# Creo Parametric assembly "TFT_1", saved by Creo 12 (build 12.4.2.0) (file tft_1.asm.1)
Units: Custom; MM, KILOGRAM, SECS

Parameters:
  PTC_WM_ITERATION = "0"
  PTC_WM_VERSION = "-.0"
  PTC_WM_LIFECYCLE_STATE = "In Work"
  PTC_WM_LIFECYCLE = "MO_CADDocument"
  PTC_WM_CREATED_BY = "Maximilian Roepper (Z0017RMS: MO)"
  PTC_WM_CREATED_ON = "18-Sep-26 11:36:42 AM"
  PTC_WM_MODIFIED_BY = "Maximilian Roepper (Z0017RMS: MO)"
  PTC_WM_MODIFIED_ON = "18-Sep-26 11:36:46 AM"
  PDMLINKNUMBER = "PDM000071455268"
  PTC_WM_NUMBER = "PDM000071455268"

Other parameters: WEIGHT, WEIGHT_FACTOR, WEIGHT_ADD, MC_ERRORS, SUPPLIER

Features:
  1. coordinate system
  2. imported feature
  3. component "TFT_CABLE_1"
  4. component "TFT_MATRIX_1"
  5. component "TFT_BOARD_1"

Other named items: DRW_VIEW_ORG, ROUGH-GROB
